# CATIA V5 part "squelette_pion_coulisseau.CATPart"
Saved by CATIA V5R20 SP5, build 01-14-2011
Part number: squelette_pion_coulisseau
Publications: "hauteur", "diametre", "Plan.1", "Point.1", "Plan.2", "Point.2", "Droite.1"
Bounding box of the stored display mesh (mm): x 0 to 0, y 0 to 42.61, z 0 to 0
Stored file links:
  F:\iao\catia\projet iao\squelette_pion_coulisseau.CATPart
  F:\iao\catia\projet iao\fhartmann.CATProduct
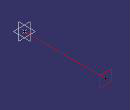
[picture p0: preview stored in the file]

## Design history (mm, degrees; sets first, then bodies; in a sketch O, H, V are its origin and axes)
Parameters
  hauteur = 42.61 mm {= External.coulisseau_largeur +External.bielle1_epaisseur +6mm}
  diametre = 10 mm {= External.bielle_diametre_int}
External parameters (linked from other documents)
  External.coulisseau_largeur = 30 mm
  External.bielle1_epaisseur = 6.61 mm
  External.bielle_diametre_int = 10 mm
Set1
  Plane1: type Offset, RefPlane zx-plane, Offset 0
  Point1: type OnPlane, Support Plane1, H 0, V 0, Direction (-1, 0, 0)
  Plane2: type Offset, RefPlane Plane1, Offset 42.61 {= hauteur}
  Point2: type OnPlane, Support Plane2, H 0, V 0, Direction (-1, 0, 0)
  Line1: type PtPt, FirstPoint Point2, SecondPoint Point1
Body1 (main body)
